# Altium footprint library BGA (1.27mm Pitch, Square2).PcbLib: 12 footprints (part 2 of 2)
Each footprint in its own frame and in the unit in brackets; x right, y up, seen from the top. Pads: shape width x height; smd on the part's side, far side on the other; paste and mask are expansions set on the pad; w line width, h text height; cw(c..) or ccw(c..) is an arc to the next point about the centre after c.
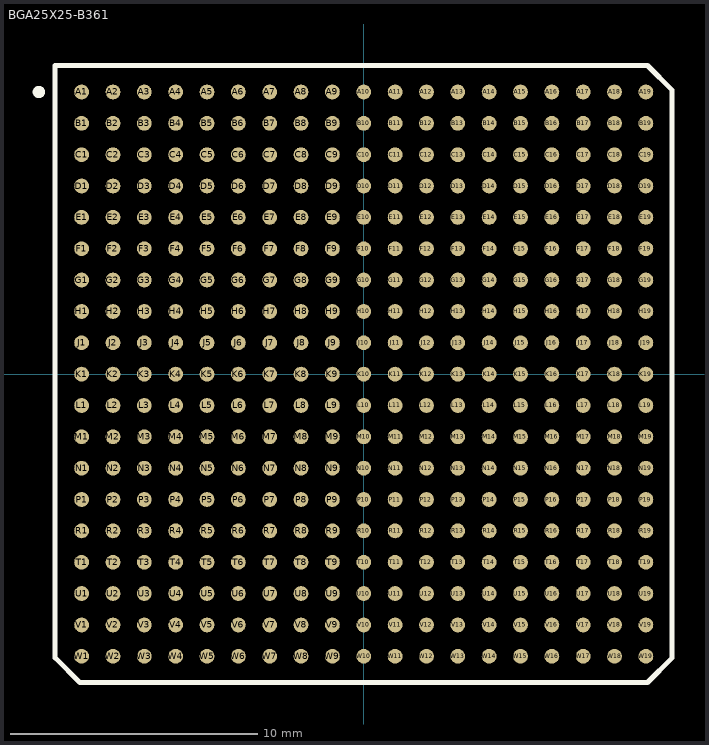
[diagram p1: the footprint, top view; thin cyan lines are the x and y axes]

## BGA25X25-B361 [mm]
pads (361):
  round 0.6 smd: A1(-11.43,11.43) A2(-10.16,11.43) A3(-8.89,11.43) A4(-7.62,11.43) A5(-6.35,11.43) A6(-5.08,11.43) A7(-3.81,11.43) A8(-2.54,11.43) A9(-1.27,11.43) A10(0,11.43) A11(1.27,11.43) A12(2.54,11.43) A13(3.81,11.43) A14(5.08,11.43) A15(6.35,11.43) A16(7.62,11.43) A17(8.89,11.43) A18(10.16,11.43) A19(11.43,11.43) B1(-11.43,10.16) B2(-10.16,10.16) B3(-8.89,10.16) B4(-7.62,10.16) B5(-6.35,10.16) B6(-5.08,10.16) B7(-3.81,10.16) B8(-2.54,10.16) B9(-1.27,10.16) B10(0,10.16) B11(1.27,10.16) B12(2.54,10.16) B13(3.81,10.16) B14(5.08,10.16) B15(6.35,10.16) B16(7.62,10.16) B17(8.89,10.16) B18(10.16,10.16) B19(11.43,10.16) C1(-11.43,8.89) C2(-10.16,8.89) C3(-8.89,8.89) C4(-7.62,8.89) C5(-6.35,8.89) C6(-5.08,8.89) C7(-3.81,8.89) C8(-2.54,8.89) C9(-1.27,8.89) C10(0,8.89) C11(1.27,8.89) C12(2.54,8.89) C13(3.81,8.89) C14(5.08,8.89) C15(6.35,8.89) C16(7.62,8.89) C17(8.89,8.89) C18(10.16,8.89) C19(11.43,8.89) D1(-11.43,7.62) D2(-10.16,7.62) D3(-8.89,7.62) D4(-7.62,7.62) D5(-6.35,7.62) D6(-5.08,7.62) D7(-3.81,7.62) D8(-2.54,7.62) D9(-1.27,7.62) D10(0,7.62) D11(1.27,7.62) D12(2.54,7.62) D13(3.81,7.62) D14(5.08,7.62) D15(6.35,7.62) D16(7.62,7.62) D17(8.89,7.62) D18(10.16,7.62) D19(11.43,7.62) E1(-11.43,6.35) E2(-10.16,6.35) E3(-8.89,6.35) E4(-7.62,6.35) E5(-6.35,6.35) E6(-5.08,6.35) E7(-3.81,6.35) E8(-2.54,6.35) E9(-1.27,6.35) E10(0,6.35) E11(1.27,6.35) E12(2.54,6.35) E13(3.81,6.35) E14(5.08,6.35) E15(6.35,6.35) E16(7.62,6.35) E17(8.89,6.35) E18(10.16,6.35) E19(11.43,6.35) F1(-11.43,5.08) F2(-10.16,5.08) F3(-8.89,5.08) F4(-7.62,5.08) F5(-6.35,5.08) F6(-5.08,5.08) F7(-3.81,5.08) F8(-2.54,5.08) F9(-1.27,5.08) F10(0,5.08) F11(1.27,5.08) F12(2.54,5.08) F13(3.81,5.08) F14(5.08,5.08) F15(6.35,5.08) F16(7.62,5.08) F17(8.89,5.08) F18(10.16,5.08) F19(11.43,5.08) G1(-11.43,3.81) G2(-10.16,3.81) G3(-8.89,3.81) G4(-7.62,3.81) G5(-6.35,3.81) G6(-5.08,3.81) G7(-3.81,3.81) G8(-2.54,3.81) G9(-1.27,3.81) G10(0,3.81) G11(1.27,3.81) G12(2.54,3.81) G13(3.81,3.81) G14(5.08,3.81) G15(6.35,3.81) G16(7.62,3.81) G17(8.89,3.81) G18(10.16,3.81) G19(11.43,3.81) H1(-11.43,2.54) H2(-10.16,2.54) H3(-8.89,2.54) H4(-7.62,2.54) H5(-6.35,2.54) H6(-5.08,2.54) H7(-3.81,2.54) H8(-2.54,2.54) H9(-1.27,2.54) H10(0,2.54) H11(1.27,2.54) H12(2.54,2.54) H13(3.81,2.54) H14(5.08,2.54) H15(6.35,2.54) H16(7.62,2.54) H17(8.89,2.54) H18(10.16,2.54) H19(11.43,2.54) J1(-11.43,1.27) J2(-10.16,1.27) J3(-8.89,1.27) J4(-7.62,1.27) J5(-6.35,1.27) J6(-5.08,1.27) J7(-3.81,1.27) J8(-2.54,1.27) J9(-1.27,1.27) J10(0,1.27) J11(1.27,1.27) J12(2.54,1.27) J13(3.81,1.27) J14(5.08,1.27) J15(6.35,1.27) J16(7.62,1.27) J17(8.89,1.27) J18(10.16,1.27) J19(11.43,1.27) K1(-11.43,0) K2(-10.16,0) K3(-8.89,0) K4(-7.62,0) K5(-6.35,0) K6(-5.08,0) K7(-3.81,0) K8(-2.54,0) K9(-1.27,0) K10(0,0) K11(1.27,0) K12(2.54,0) K13(3.81,0) K14(5.08,0) K15(6.35,0) K16(7.62,0) K17(8.89,0) K18(10.16,0) K19(11.43,0) L1(-11.43,-1.27) L2(-10.16,-1.27) L3(-8.89,-1.27) L4(-7.62,-1.27) L5(-6.35,-1.27) L6(-5.08,-1.27) L7(-3.81,-1.27) L8(-2.54,-1.27) L9(-1.27,-1.27) L10(0,-1.27) L11(1.27,-1.27) L12(2.54,-1.27) L13(3.81,-1.27) L14(5.08,-1.27) L15(6.35,-1.27) L16(7.62,-1.27) L17(8.89,-1.27) L18(10.16,-1.27) L19(11.43,-1.27) M1(-11.43,-2.54) M2(-10.16,-2.54) M3(-8.89,-2.54) M4(-7.62,-2.54) M5(-6.35,-2.54) M6(-5.08,-2.54) M7(-3.81,-2.54) M8(-2.54,-2.54) M9(-1.27,-2.54) M10(0,-2.54) M11(1.27,-2.54) M12(2.54,-2.54) M13(3.81,-2.54) M14(5.08,-2.54) M15(6.35,-2.54) M16(7.62,-2.54) M17(8.89,-2.54) M18(10.16,-2.54) M19(11.43,-2.54) N1(-11.43,-3.81) N2(-10.16,-3.81) N3(-8.89,-3.81) N4(-7.62,-3.81) N5(-6.35,-3.81) N6(-5.08,-3.81) N7(-3.81,-3.81) N8(-2.54,-3.81) N9(-1.27,-3.81) N10(0,-3.81) N11(1.27,-3.81) N12(2.54,-3.81) N13(3.81,-3.81) N14(5.08,-3.81) N15(6.35,-3.81) N16(7.62,-3.81) N17(8.89,-3.81) N18(10.16,-3.81) N19(11.43,-3.81) P1(-11.43,-5.08) P2(-10.16,-5.08) P3(-8.89,-5.08) P4(-7.62,-5.08) P5(-6.35,-5.08) P6(-5.08,-5.08) P7(-3.81,-5.08) P8(-2.54,-5.08) P9(-1.27,-5.08) P10(0,-5.08) P11(1.27,-5.08) P12(2.54,-5.08) P13(3.81,-5.08) P14(5.08,-5.08) P15(6.35,-5.08) P16(7.62,-5.08) P17(8.89,-5.08) P18(10.16,-5.08) P19(11.43,-5.08) R1(-11.43,-6.35) R2(-10.16,-6.35) R3(-8.89,-6.35) R4(-7.62,-6.35) R5(-6.35,-6.35) R6(-5.08,-6.35) R7(-3.81,-6.35) R8(-2.54,-6.35) R9(-1.27,-6.35) R10(0,-6.35) R11(1.27,-6.35) R12(2.54,-6.35) R13(3.81,-6.35) R14(5.08,-6.35) R15(6.35,-6.35) R16(7.62,-6.35) R17(8.89,-6.35) R18(10.16,-6.35) R19(11.43,-6.35) T1(-11.43,-7.62) T2(-10.16,-7.62) T3(-8.89,-7.62) T4(-7.62,-7.62) T5(-6.35,-7.62) T6(-5.08,-7.62) T7(-3.81,-7.62) T8(-2.54,-7.62) T9(-1.27,-7.62) T10(0,-7.62) T11(1.27,-7.62) T12(2.54,-7.62) T13(3.81,-7.62) T14(5.08,-7.62) T15(6.35,-7.62) T16(7.62,-7.62) T17(8.89,-7.62) T18(10.16,-7.62) T19(11.43,-7.62) U1(-11.43,-8.89) U2(-10.16,-8.89) U3(-8.89,-8.89) U4(-7.62,-8.89) U5(-6.35,-8.89) U6(-5.08,-8.89) U7(-3.81,-8.89) U8(-2.54,-8.89) U9(-1.27,-8.89) U10(0,-8.89) U11(1.27,-8.89) U12(2.54,-8.89) U13(3.81,-8.89) U14(5.08,-8.89) U15(6.35,-8.89) U16(7.62,-8.89) U17(8.89,-8.89) U18(10.16,-8.89) U19(11.43,-8.89) V1(-11.43,-10.16) V2(-10.16,-10.16) V3(-8.89,-10.16) V4(-7.62,-10.16) V5(-6.35,-10.16) V6(-5.08,-10.16) V7(-3.81,-10.16) V8(-2.54,-10.16) V9(-1.27,-10.16) V10(0,-10.16) V11(1.27,-10.16) V12(2.54,-10.16) V13(3.81,-10.16) V14(5.08,-10.16) V15(6.35,-10.16) V16(7.62,-10.16) V17(8.89,-10.16) V18(10.16,-10.16) V19(11.43,-10.16) W1(-11.43,-11.43) W2(-10.16,-11.43) W3(-8.89,-11.43) W4(-7.62,-11.43) W5(-6.35,-11.43) W6(-5.08,-11.43) W7(-3.81,-11.43) W8(-2.54,-11.43) W9(-1.27,-11.43) W10(0,-11.43) W11(1.27,-11.43) W12(2.54,-11.43) W13(3.81,-11.43) W14(5.08,-11.43) W15(6.35,-11.43) W16(7.62,-11.43) W17(8.89,-11.43) W18(10.16,-11.43) W19(11.43,-11.43)
Top Overlay:
  circle w0.25: c-13.16,11.43 r0.125
  lines w0.2: -12.505,-11.495 -11.505,-12.495 11.495,-12.495 12.495,-11.495 12.495,11.505 11.495,12.505 -12.505,12.505 -12.505,-11.495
